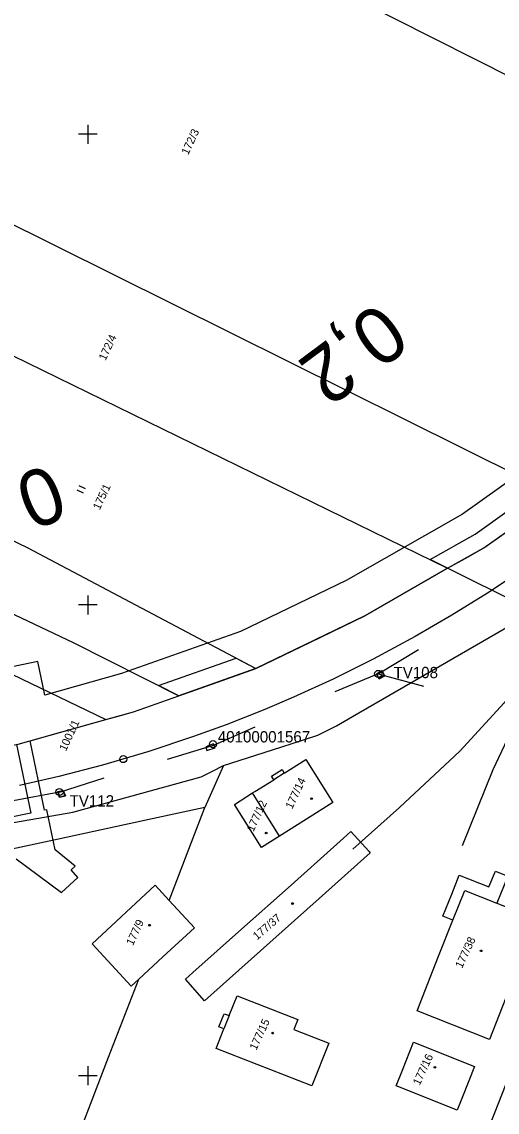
# Model space of a CAD drawing. Extents: x -755344 to -754412, y -1162670 to -1161477.
# Drawn here: x -755014.1 to -754912.9, y -1162307.8 to -1162076.1 of the extents above; entities that cross this region are included whole.
import ezdxf

# ---------------------------------------------------------------- set-up
doc = ezdxf.new("R2010")
doc.units = 0
for name, color, linetype in [('Body ŽBP', 7, 'Continuous'), ('hranice obvodu stavby', 7, 'Continuous'), ('Staniceni a namezniky', 7, 'Continuous'), ('Síť', 7, 'Continuous'), ('TZ_ostatní', 7, 'Continuous'), ('Vrstva 1', 7, 'Continuous'), ('Vrstva 12', 7, 'Continuous'), ('Vrstva 53', 7, 'Continuous'), ('Vrstva 55', 7, 'Continuous'), ('Vrstva 56', 7, 'Continuous'), ('Vrstva 57', 7, 'Continuous'), ('Vrstva 58', 7, 'Continuous'), ('Vrstva 59', 7, 'Continuous')]:
    doc.layers.add(name, color=color, linetype=linetype)

msp = doc.modelspace()

# ---------------------------------------------------------------- linework, layer by layer
at = {"layer": 'Body ŽBP'}
for p, q in [((-754938.26, -1162214.64), (-754929.7, -1162209.47)), ((-754938.26, -1162214.64), (-754947.49, -1162218.48)), ((-754938.24, -1162214.59), (-754938.28, -1162214.69)), ((-754938.26, -1162214.64), (-754938.26, -1162214.64)), ((-754938.26, -1162214.64), (-754928.6, -1162217.25)), ((-754973.58, -1162229.89), (-754964.4, -1162225.92)), ((-754973.58, -1162229.89), (-754983.15, -1162232.79)), ((-754973.58, -1162229.89), (-754973.58, -1162229.89)), ((-754973.37, -1162229.51), (-754973.41, -1162229.6)), ((-754973.39, -1162229.56), (-754973.39, -1162229.56)), ((-755006.05, -1162239.73), (-754996.51, -1162236.75)), ((-755006.05, -1162239.73), (-755015.88, -1162241.57)), ((-755006.03, -1162239.68), (-755006.07, -1162239.78)), ((-755006.05, -1162239.73), (-755006.05, -1162239.73))]:
    msp.add_line(p, q, dxfattribs=at)
for centre in [(-754938.26, -1162214.64), (-754973.39, -1162229.56), (-755006.05, -1162239.73)]:
    msp.add_circle(centre, 0.756, dxfattribs=at)
at = {"layer": 'hranice obvodu stavby'}
for points in [[(-754868.42, -1162135.23), (-754868.42, -1162135.42), (-754885.14, -1162151.61), (-754890.41, -1162145.41), (-754900.32, -1162153.82), (-754894.5, -1162160.68), (-754900.94, -1162166.91), (-754920.36, -1162180.69), (-754945.08, -1162194.78), (-754967.54, -1162205.63), (-754992.85, -1162214.58), (-755009.16, -1162219.14), (-755010.64, -1162212), (-755023.37, -1162214.63)], [(-755012.26, -1162228.83), (-755005.53, -1162226.95), (-754996.22, -1162224.35), (-754993.26, -1162223.52), (-754990.29, -1162222.69), (-754985.46, -1162220.99), (-754980.63, -1162219.28), (-754972.45, -1162216.39), (-754964.26, -1162213.49), (-754952.69, -1162207.9), (-754941.12, -1162202.31), (-754923.5, -1162192.2), (-754919.64, -1162190.04), (-754915.78, -1162187.87), (-754907.92, -1162182.32)], [(-755015.16, -1162229.61), (-755012.14, -1162244.2), (-755017.04, -1162245.22)], [(-755015.23, -1162253.93), (-755005.62, -1162261.05), (-755002.11, -1162257.86), (-755003.57, -1162256.25), (-755002.73, -1162255.48), (-755006.94, -1162252.04), (-755008.71, -1162243.49), (-755009.2, -1162243.6), (-755012.26, -1162228.83)]]:
    msp.add_lwpolyline(points, dxfattribs=at)
at = {"layer": 'Staniceni a namezniky'}
msp.add_circle((-754992.48, -1162232.74), 0.75, dxfattribs=at)
at = {"layer": 'Síť'}
for points in [[(-755000, -1162098), (-755000, -1162100), (-755000, -1162102)], [(-754998, -1162100), (-755000, -1162100), (-755002, -1162100)], [(-755000, -1162198), (-755000, -1162200), (-755000, -1162202)], [(-754998, -1162200), (-755000, -1162200), (-755002, -1162200)], [(-754998, -1162300), (-755000, -1162300), (-755002, -1162300)], [(-755000, -1162298), (-755000, -1162300), (-755000, -1162302)]]:
    msp.add_lwpolyline(points, dxfattribs=at)
at = {"layer": 'TZ_ostatní'}
msp.add_lwpolyline([(-754923.5, -1162192.2), (-754927.24, -1162190.37), (-754917.66, -1162184.92), (-754903.67, -1162174.98), (-754894.6, -1162165.92), (-754868.47, -1162140.62), (-754868.56, -1162149.23)], dxfattribs=at)
msp.add_lwpolyline([(-754984.97, -1162217.1), (-754968.47, -1162211.27), (-754964.26, -1162213.49), (-754980.63, -1162219.28)], close=True, dxfattribs=at)
at = {"layer": 'Vrstva 1'}
for points in [[(-754906.67, -1162191.94), (-754914.99, -1162197.47), (-754922.58, -1162202.18), (-754930.39, -1162206.7), (-754939.31, -1162211.5), (-754947.84, -1162215.73), (-754956.28, -1162219.59), (-754962.4, -1162222.2), (-754970.58, -1162225.44), (-754977.51, -1162227.97), (-754987.04, -1162231.13), (-754996.89, -1162234.04), (-755006.19, -1162236.46), (-755014.55, -1162238.36)], [(-754904.65, -1162212.5), (-754911.48, -1162220.81), (-754920.93, -1162231.04), (-754933.71, -1162243.01), (-754943.62, -1162251.86)], [(-754903.04, -1162213.58), (-754907.06, -1162220.68), (-754913.9, -1162235.02), (-754920.39, -1162251.15)]]:
    msp.add_lwpolyline(points, dxfattribs=at)
at = {"layer": 'Vrstva 12'}
for p, q in [((-755006.36, -1162239.65), (-755005.98, -1162240.86)), ((-755005.26, -1162239.4), (-755004.8, -1162240.56))]:
    msp.add_line(p, q, dxfattribs=at)
for points in [[(-754938.61, -1162214.62), (-754937.47, -1162213.93), (-754936.93, -1162214.98), (-754938.12, -1162215.62), (-754938.61, -1162214.62)], [(-754938.61, -1162214.62), (-754938.06, -1162215.69), (-754936.87, -1162215.08), (-754937.47, -1162213.93)], [(-754938.12, -1162215.62), (-754938.06, -1162215.69)], [(-754936.93, -1162214.98), (-754936.87, -1162215.08)], [(-754974.93, -1162230.1), (-754974.68, -1162230.94), (-754972.95, -1162230.35), (-754973.28, -1162229.5), (-754974.93, -1162230.1)], [(-755006.36, -1162239.65), (-755005.26, -1162239.4), (-755005, -1162240.57), (-755006.05, -1162240.87), (-755006.36, -1162239.65)], [(-755006.05, -1162240.87), (-755005.98, -1162240.86), (-755004.8, -1162240.56), (-755005, -1162240.57)]]:
    msp.add_lwpolyline(points, dxfattribs=at)
at = {"layer": 'Vrstva 53'}
msp.add_lwpolyline([(-755014.83, -1162229.55), (-754996.22, -1162224.35), (-754990.29, -1162222.69), (-754980.63, -1162219.28), (-754964.26, -1162213.49), (-754941.12, -1162202.31), (-754923.5, -1162192.2), (-754915.78, -1162187.87), (-754900.06, -1162176.77), (-754896.07, -1162173.88), (-754868.56, -1162149.23), (-754862.16, -1162142.69), (-754861.18, -1162138.93), (-754868.42, -1162135.23), (-754868.4, -1162133.56), (-754865.75, -1162126.5), (-754858.37, -1162113.93), (-754854.71, -1162107.25), (-754837.06, -1162081.94), (-754828.75, -1162070.02)], dxfattribs=at)
at = {"layer": 'Vrstva 55'}
for p, q in [((-755075.64, -1162089.56), (-754900.06, -1162176.77)), ((-755078.18, -1162116.73), (-754923.5, -1162192.2)), ((-754905.78, -1162201), (-754923.5, -1162192.2)), ((-754980.63, -1162219.28), (-754964.26, -1162213.49)), ((-754959.28, -1162249.1), (-754965.02, -1162239.9))]:
    msp.add_line(p, q, dxfattribs=at)
for points in [[(-754858.37, -1162113.93), (-755045.32, -1162019.78), (-755064.79, -1162013.41)], [(-755081.87, -1162157.32), (-755051.44, -1162169.33), (-755012.93, -1162187.79), (-754964.26, -1162213.49)], [(-755083.38, -1162173.92), (-755054.32, -1162183.78), (-755003.14, -1162207.94), (-754980.63, -1162219.28)], [(-754923.5, -1162192.2), (-754915.78, -1162187.87), (-754900.06, -1162176.77)], [(-755084.35, -1162184.59), (-755063.67, -1162192.69), (-755040.35, -1162203.08), (-754996.22, -1162224.35)], [(-754923.5, -1162192.2), (-754941.12, -1162202.31), (-754964.26, -1162213.49)], [(-754971.15, -1162234.1), (-754958.95, -1162230.19), (-754951.07, -1162227.67), (-754947.14, -1162225.65), (-754943.74, -1162223.69), (-754908.27, -1162203.24), (-754905.78, -1162201)], [(-754996.22, -1162224.35), (-754990.29, -1162222.69), (-754980.63, -1162219.28)], [(-754878.41, -1162219.27), (-754890.63, -1162250.1), (-754895.21, -1162261.65), (-754899.8, -1162273.21), (-754904.37, -1162284.73), (-754908.92, -1162296.21), (-754913.49, -1162307.74), (-754920.81, -1162326.21)], [(-755017.58, -1162230.07), (-755014.83, -1162229.55), (-754996.22, -1162224.35)], [(-754965.02, -1162239.9), (-754964.51, -1162239.63), (-754960.48, -1162237.12), (-754960.95, -1162236.39), (-754958.69, -1162234.97), (-754958.23, -1162235.71), (-754953.68, -1162232.85), (-754947.93, -1162241.97), (-754953.52, -1162245.48), (-754959.28, -1162249.1)], [(-755085.12, -1162252.75), (-755070.73, -1162253.01), (-755038.01, -1162250.05), (-755036.82, -1162249.84), (-755013.79, -1162245.86), (-755003.23, -1162244.03), (-754994.22, -1162241.55), (-754975.93, -1162236.51), (-754973.51, -1162235.29), (-754971.15, -1162234.1)], [(-754971.15, -1162234.1), (-754972, -1162236.02), (-754975.1, -1162243.04)], [(-754959.28, -1162249.1), (-754963.09, -1162251.49), (-754968.85, -1162242.38), (-754965.02, -1162239.9)], [(-754975.1, -1162243.04), (-754986.3, -1162245.44), (-755006.22, -1162249.72), (-755027.5, -1162254.28), (-755031.53, -1162255.15), (-755065.07, -1162258.01), (-755070.25, -1162259.31)], [(-754982.72, -1162262.75), (-754982.38, -1162261.87), (-754977.59, -1162249.49), (-754975.1, -1162243.04)], [(-754956.8, -1162259.49), (-754945.64, -1162249.55), (-754944.05, -1162248.14), (-754940.25, -1162252.33), (-754939.94, -1162252.67), (-754950.82, -1162262.37), (-754961.31, -1162271.72), (-754971.86, -1162281.13), (-754975.18, -1162284.09), (-754979.27, -1162279.5), (-754977.67, -1162278.08), (-754967.36, -1162268.89), (-754956.8, -1162259.49)], [(-754922.63, -1162261.43), (-754921.01, -1162257.39), (-754914.72, -1162259.89), (-754913.29, -1162256.54), (-754910.69, -1162257.6), (-754913.05, -1162263.33), (-754904.47, -1162266.73), (-754905.81, -1162270.11), (-754910.45, -1162281.8), (-754914.62, -1162292.29), (-754930, -1162286.19), (-754925.41, -1162274.6), (-754922.38, -1162266.96), (-754924.5, -1162266.11), (-754922.63, -1162261.43)], [(-754989.19, -1162279.49), (-754990.78, -1162280.96), (-754999.09, -1162271.99), (-754985.67, -1162259.55), (-754982.72, -1162262.75)], [(-754982.72, -1162262.75), (-754977.34, -1162268.59), (-754984.03, -1162274.74), (-754989.19, -1162279.49)], [(-754991.59, -1162355.66), (-755009.14, -1162331.11), (-755004.94, -1162320.25), (-754995.6, -1162296.07), (-754989.19, -1162279.49)], [(-754956.18, -1162290.17), (-754948.75, -1162293.08), (-754952.39, -1162302.17), (-754972.72, -1162294.22), (-754971.08, -1162290.06), (-754972.13, -1162289.65), (-754971, -1162286.83), (-754969.96, -1162287.23), (-754968.29, -1162283), (-754955.36, -1162288.07), (-754956.18, -1162290.17)], [(-754930.78, -1162292.9), (-754917.8, -1162298.01), (-754920.35, -1162304.49), (-754921.45, -1162307.29), (-754934.43, -1162302.13), (-754933.11, -1162298.79), (-754930.78, -1162292.9)]]:
    msp.add_lwpolyline(points, dxfattribs=at)
at = {"layer": 'Vrstva 56'}
for p, q in [((-754958.23, -1162235.71), (-754960.48, -1162237.12)), ((-754969.96, -1162287.23), (-754971.08, -1162290.06))]:
    msp.add_line(p, q, dxfattribs=at)
msp.add_lwpolyline([(-754922.38, -1162266.96), (-754919.87, -1162260.62), (-754913.05, -1162263.33)], dxfattribs=at)
at = {"layer": 'Vrstva 58'}
for p, q in [((-755000.5, -1162175.35), (-755001.86, -1162174.72)), ((-755000.92, -1162176.26), (-755002.28, -1162175.63))]:
    msp.add_line(p, q, dxfattribs=at)
at = {"layer": 'Vrstva 59'}
for centre in [(-754952.44, -1162241.15), (-754962.08, -1162248.45), (-754956.47, -1162263.43), (-754986.89, -1162268.03), (-754916.37, -1162273.47), (-754960.7, -1162290.95), (-754926.2, -1162298.21)]:
    msp.add_circle(centre, 0.175, dxfattribs=at)

# ---------------------------------------------------------------- texts
at = {"layer": 'Body ŽBP'}
for s, p in [(' TV108', (-754935.89, -1162215.55)), (' 40100001567', (-754973.26, -1162229.2)), (' TV112', (-755004.78, -1162242.81))]:
    msp.add_text(s, height=2.4, dxfattribs=at).set_placement(p)
at = {"layer": 'Staniceni a namezniky'}
for s, rotation, p in [('0,2', 216.7166, (-754938.04, -1162135.28)), ('0,3', 201.4151, (-755007.99, -1162169.85))]:
    msp.add_text(s, height=12, rotation=rotation, dxfattribs=at).set_placement(p)
at = {"layer": 'Vrstva 57'}
for s, rotation, p in [('172/3', 65, (-754978.68, -1162104.52)), ('172/4', 65, (-754996.26, -1162148.21)), ('175/1', 65, (-754997.49, -1162179.94)), ('1001/1', 65, (-755004.68, -1162231.19)), ('177/14', 65, (-754956.55, -1162243.48)), ('177/12', 65, (-754964.8, -1162248.3)), ('177/9', 65, (-754990.43, -1162272.48)), ('177/37', 40.664, (-754964.03, -1162271.28)), ('177/38', 65, (-754920.43, -1162277.31)), ('177/15', 65, (-754964.2, -1162294.72)), ('177/16', 65, (-754929.45, -1162302.18))]:
    msp.add_text(s, height=1.7, rotation=rotation, dxfattribs=at).set_placement(p)

doc.saveas('drawing.dxf')
